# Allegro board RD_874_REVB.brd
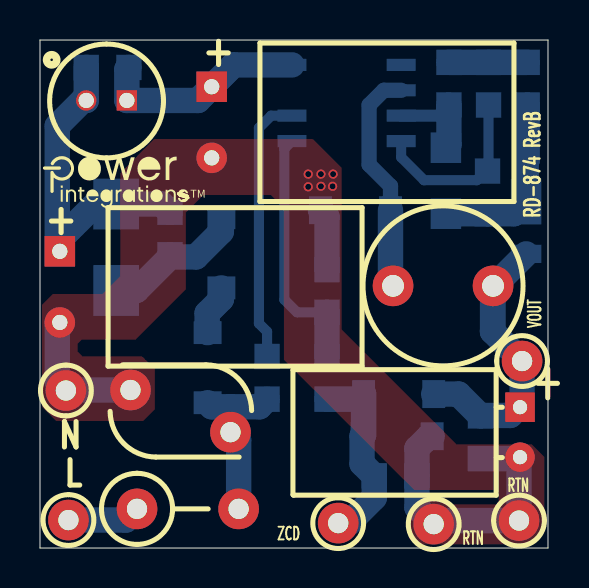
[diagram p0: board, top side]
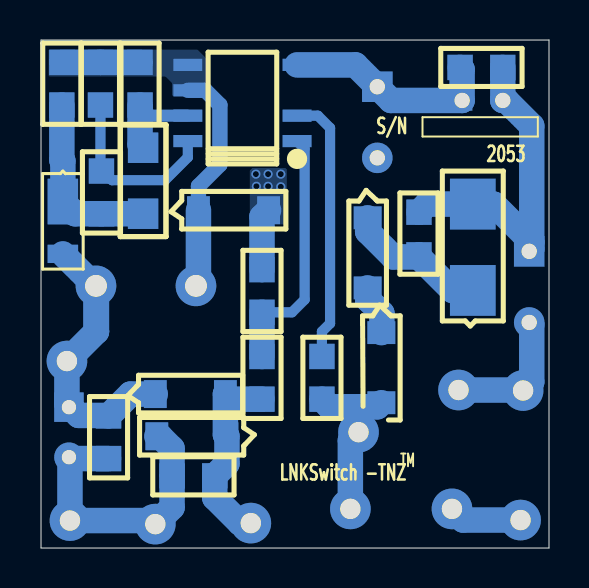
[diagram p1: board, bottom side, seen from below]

Outline 25.4 x 25.4 mm; copper layers: TOP, BOTTOM. Coordinates in mm from the lower left corner of the outline.
Outline path: 0,25.4 25.4,25.4 25.4,0 0,0 0,25.4

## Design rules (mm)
constraint set DEFAULT: min track width 0.508

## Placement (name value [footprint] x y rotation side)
C1  1.0 uF  [PIPOLCAPCLYD320LS140030]  8.59 21.29 270 top
C2  100 nF  [PISMC0805]  20.45 22.15 90 bottom
C3  10 uF  [PISMC0805]  24.36 22.15 90 bottom
C4  100 uF  [PIPOLCAPCLYD248LS098028]  24 5.79 270 top
C5  100 pF  [PISMC0805]  14.35 11.79 90 bottom
C6  1.0 uF  [PIPOLCAPCLYD320LS140030]  0.99 13.06 270 top
C7  optional  [PISMC0805]  16.71 3.61 0 bottom
D1  SM4007PL-TP  [PI_SM_SOD-123_12]  8.38 10.77 270 bottom
D2  SFM18PL-TP  [PI_SM_SOD-123_12]  17.53 16.89 180 bottom
D3  DFLR1600-7  [PISMDDFLR120012]  24.31 17.35 90 bottom
D4  SM4001PL-TP  [PI_SM_SOD-123_12]  19.68 7.7 180 bottom
D5  SM4001PL-TP  [PI_SM_SOD-123_12]  16.1 5.59 0 bottom
D6  SM4007PL-TP  [PI_SM_SOD-123_12]  9.07 16.51 270 bottom
L1  2.7 mH  [PI_CHOKE_VD8P0H7P5LS5P0D0P6]  17.65 13.11 0 top
L2  2.2 mH  [PI_CHOKE_RL5480-1_D2]  4.34 22.38 180 top
NOREF  -  []  -0.41 19.48 0 top
NOREF#2  -  []  25.4 0 90 top
NOREF#3  -  []  0 0 0 top
NOREF#4  -  []  -228.6 -144.78 0 top
NOREF#5  -  []  -150.78 54.23 0 top
R1  18 k  [PISMR0805]  6.5 16.79 270 bottom
R2  1 M  [PISMR0805]  11.35 9.58 270 bottom
R3  20.0 k  [PISMR1206]  20.29 20.02 270 bottom
R4  40.2 k  [PISMR0805]  22.43 22.15 90 bottom
R5  44.2 k  [PISMR0805]  22.38 16.71 90 bottom
R6  100 k  [PISMR0805]  14.35 9.58 270 bottom
R7  20 k  [PISMR0805]  22.02 6.6 270 bottom
R8  4.7 k  [PISMR0805]  2.31 24.03 0 bottom
RF1  8.2  [PI12WRESD180LS575040]  4.85 1.96 0 top
RV1  300 Vac  [PI_DISC276X181_LS200X83D040]  9.53 5.79 180 top
TP1  BLK  [PITPKEYSTONE100X100]  1.42 1.4 0 top
TP2  WHT  [PITPKEYSTONE100X100]  1.3 7.87 0 top
TP3  RED  [PITPKEYSTONE100X100]  24.1 9.35 90 top
TP4  BLUE  [PITPKEYSTONE100X100]  14.91 1.24 0 top
TP5  BLK  [PITPKEYSTONE100X100]  23.95 1.37 90 top
TP6  BLK  [PITPKEYSTONE100X100]  19.68 1.19 0 top
U1  LNK3302  [PISMSO8_NOP3]  12.6 20.35 90 bottom
VR1  SMAZ10-13-F  [PISMDO214AC12]  3.81 12.88 90 bottom

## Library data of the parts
C1 C6 = CAP POL: alternate symbols: (pipolcapclyd320ls140030h)
C2 C3 C5 C7 = CAP NP
C4 = CAP POL: alternate symbols: (pipolcapclyd248ls098028_h)
D1-D3 D6 = DIODE
D4 D5 = DIODE: room: 2
L1 = INDUCTOR
L2 = INDUCTOR_DOT2
R1 R3 R5 = R
R2 R6 R8 = R: room: 1
R4 R7 = R: tolerance: 1%
RF1 = RF: alternate symbols: (pi1wvresd120ls200d040)
RV1 = VARISTOR
TP1 TP2 TP4-TP6 = TESTPOINT
TP3 = TESTPOINT: room: 2
U1 = LNK-TNZ
VR1 = DIODE_ZENER

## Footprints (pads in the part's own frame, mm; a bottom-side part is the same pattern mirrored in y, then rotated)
PI12WRESD180LS575040
  round 2.032 hole 1.016: 1(0,0) 2(5.08,0)
PI_CHOKE_RL5480-1_D2
  rect 1.016x1.016 hole 0.762: 1(0,0)
  round 1.016 hole 0.762: 2(2.032,0)
PI_CHOKE_VD8P0H7P5LS5P0D0P6
  round 2.032 hole 1.092: 1(0,0) 2(5,0)
PI_DISC276X181_LS200X83D040
  round 2.032 hole 1.016: 1(0,0) 2(5.001,-2.108)
PI_SM_SOD-123_12
  rect 1.143x1.397 smd: 1(0,0) 2(3.505,0)
PIPOLCAPCLYD248LS098028
  rect 1.473x1.473 hole 0.711: 1(-1.25,0)
  round 1.473 hole 0.711: 2(1.25,0)
PIPOLCAPCLYD320LS140030
  rect 1.524x1.524 hole 0.762: 1(-1.778,0)
  round 1.524 hole 0.762: 2(1.778,0)
PISMC0805
  rect 1.27x1.27 smd: 1(0,0) 2(2.134,0)
PISMDDFLR120012
  rect 2.286x1.524 smd: 1(-0.025,0)
  rect 0.914x1.524 smd: 2(-2.642,0)
PISMDO214AC12
  rect 2.54x2.286 smd: 1(0,0) 2(4.318,0)
PISMR0805
  rect 1.27x1.27 smd: 1(0,0) 2(2.134,0)
PISMR1206
  rect 1.524x1.524 smd: 1(0,0) 2(3.302,0)
PISMSO8_NOP3
  rect 0.61x1.448 smd: 1(0,0) 2(1.27,0) 4(3.81,0) 5(3.81,5.461) 6(2.54,5.461) 7(1.27,5.461) 8(0,5.461)
PITPKEYSTONE100X100
  round 2.032 hole 1.016: 1(0,0)

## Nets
N361382: D6.1 R1.2 VR1.1
N361822: C1.2 C4.2 C5.2 C6.2 C7.2 D2.2 D5.2 R7.2 RV1.2 TP2.1 TP5.1 TP6.1
N595771: D1.2 R2.2 RF1.2 RV1.1
N596154: RF1.1 TP1.1
N596955: C2.1 R3.1 U1.7
N596963: C3.1 D3.1 R3.2 R5.1
N597007: R4.1 R5.2 U1.8
N597039: C4.1 D3.2 D4.1 L1.2 R7.1 TP3.1
N597117: C2.2 C3.2 D2.1 L1.1 R4.2 U1.5 U1.6
N597183: C1.1 L2.1 R8.2 U1.4
N597938: C6.1 L2.2 R1.1 R8.1 VR1.2
N605807: R2.1 U1.2
N607999: C7.1 D4.2 D5.1 R6.2 TP4.1
N609815: C5.1 R6.1 U1.1
N615244: D1.1 D6.2

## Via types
v1: diameter 0.457, hole 0.305, TOP to BOTTOM, 6 vias

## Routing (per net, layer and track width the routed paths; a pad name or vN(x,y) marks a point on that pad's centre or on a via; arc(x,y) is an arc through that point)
N361382: length 7.3
  BOTTOM w1.27: D6.1 9.07,15.82 7.8,14.55 6.6,14.55 R1.2 6.5,14.55 4.83,12.88 VR1.1
N361822: length 24.6
  BOTTOM w1.27: C6.2 0.86,11.15 0.86,8.31 TP2.1 1.32,7.9 RV1.2 ; D5.2 19.46,5.59 18.85,4.98 C7.2 18.85,2.03 TP6.1 19.86,1.37 TP5.1 23.95,4.57 23.86,4.47 R7.2 ; D2.2 14.35,16.56 C5.2
  vias: v1(13.41,18.69) v1(13.41,18.06) v1(14.05,18.69) v1(14.05,18.08) v1(14.63,18.08) v1(14.66,18.69)
N595771: length 8.5
  BOTTOM w1.27: RF1.2 9.93,5.38 RV1.1 9.53,5.79 9.53,7.06 ; 9.53,7.06 10.97,7.06 R2.2 ; 9.53,7.06 8.59,7.06 D1.2
N596154: length 3.7
  BOTTOM w1.27: RF1.1 4.29,1.4 TP1.1
N596955: length 4.8
  BOTTOM w0.6: C2.1 19.91,21.62 U1.7
  BOTTOM w1.27: C2.1 20.45,20.17 R3.1
N596963: length 9.1
  BOTTOM w1.27: C3.1 24.36,19.41 24.31,19.35 D3.1 23.7,16.71 R5.1 R3.2
N597007: length 9.1
  BOTTOM w0.508: U1.8 18.06,19.53 19.2,18.39 21.84,18.39 22.3,18.85 R5.2 22.38,18.92 22.43,18.97 R4.1
N597039: length 20.4
  BOTTOM w0.508: 23.95,7.07 23.77,7.07 23.31,6.6 R7.1 ; TP3.1 24,9.25 C4.1
  BOTTOM w1.27: 22,6.63 23.51,6.63 24.1,7.22 TP3.1 22.63,10.82 ; 22,6.63 R7.1 ; 22,6.63 20.93,7.7 D4.1 ; 22.63,10.82 22.65,10.85 L1.2 22.71,13.11 D3.2 ; 22.63,10.82 22.63,12.83
N597117: length 15.4
  BOTTOM w0.762: D2.1 17.53,18.1 16.46,19.17 16.46,22.15 17.19,22.89 U1.6
  BOTTOM w1.27: D2.1 17.53,13.23 L1.1 ; C3.2 R4.2 C2.2
N597183: length 10.7
  BOTTOM w1.27: U1.4 9.68,24.16 C1.1 7.9,22.38 L2.1 4.34,23.93 R8.2
N597938: length 16.5
  BOTTOM w1.27: 0.86,15.29 2.77,17.2 VR1.2 6.1,17.2 R1.1 ; 0.86,15.29 0.86,14.96 C6.1 ; 0.86,15.29 0.86,21.11 2.13,22.38 L2.2 R8.1
N605807: length 13.5
  BOTTOM w0.508: R2.1 11.35,10.82 10.95,11.23 10.95,21.01 11.56,21.62 U1.2
N607999: length 9.7
  BOTTOM w1.27: R6.2 15.93,7.44 D4.2 16.18,5.66 D5.1 16.1,4.22 C7.1 16.71,2.51 15.44,1.24 TP4.1
N609815: length 12.7
  BOTTOM w0.508: C5.1 12.85,11.79 12.22,12.42 12.22,19.96 U1.1
  BOTTOM w1.27: C5.1 R6.1
N615244: length 2.5
  BOTTOM w1.27: D6.2 9.07,12.45 8.36,11.73 8.36,10.79 D1.1

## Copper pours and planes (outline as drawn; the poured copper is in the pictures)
N361822 on TOP: 24.59,5.18 20.83,5.18 15.09,10.92 15.09,19 13.64,20.45 5.71,20.45 4.01,18.75 4.01,13.59 3.12,12.7 0.64,12.7 0.1,12.17 0.1,7.06 0.81,6.35 5.16,6.35 5.74,6.93 5.74,8.94 5.11,9.58 2.13,9.58 1.88,9.83 1.88,10.21 2.08,10.41 4.78,10.41 7.29,12.93 7.29,16.79 7.32,16.79 8.18,17.65 11.53,17.65 12.19,16.99 12.19,9.42 18.72,2.9 22.78,2.9 22.94,2.74 22.94,2.26 22.86,2.18 20.55,2.18 20.22,2.51 19.18,2.51 18.47,1.8 18.47,0.48 18.77,0.18 24.51,0.18 25.22,0.89 25.22,4.55
N361822 on BOTTOM: 13.18,19 14.83,19 14.96,18.87 14.96,16.23 14.91,16.18 13.28,16.18 13.11,16.36 13.11,18.92
N597117 on BOTTOM: 24.99,24.92 17.58,24.92 17.14,24.49 17.14,22.73 17.27,22.61 18.82,22.61 18.85,22.63 18.85,23.24 19.18,23.57 24.97,23.57 25.02,23.62 25.02,24.89

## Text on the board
Ref Des/Silkscreen Bottom: TM | 2053 | S/N | LNKSwitch -TNZ
Ref Des/Silkscreen Top: ZCD | RTN | VOUT | RD-874 RevB | N | L
FAB_NOTES: 14.  FAB HOUSE LOGO,DATE CODE TO BE IN SILK SCREEN ONLY.DO NOT USE COPPER. | 13.  MATERIAL FR4 COPPER 2oz THICKNESS 0.062" | PLEASE DELETE THIS PIN
User.8: FIGURE | FINISHED_SIZE | 0.3048 | 0.7112 | 0.762 | 1.016 | DRILL CHART: TOP to BOTTOM | ALL UNITS ARE IN MILLIMETERS | TOLERANCE_DRILL | +0.0762/-0.0762 | +0.0/-0.0 | PLATED | QTY | 6 | 2 | 10 | 26 | TOTAL HOLES:
